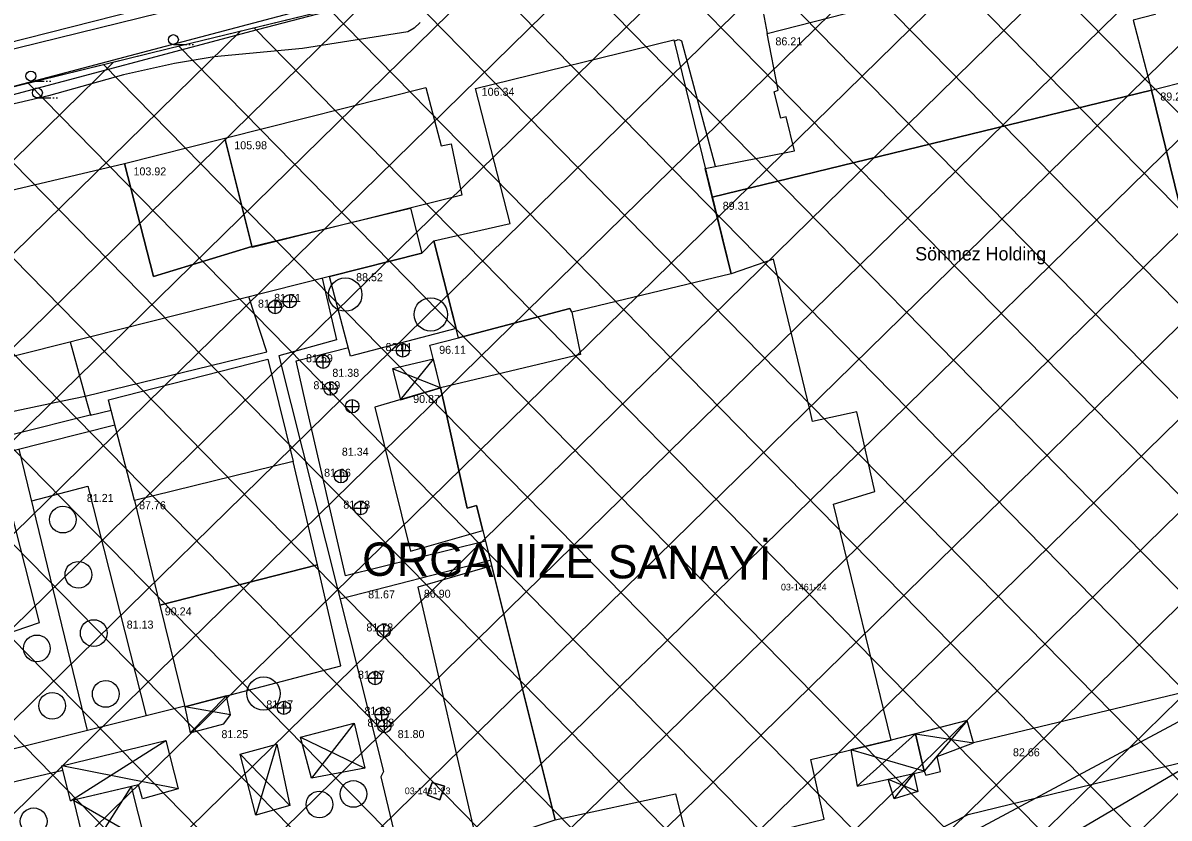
# Model space of a CAD drawing. Extents: x 412225 to 413380, y 4456471 to 4457189.
# Drawn here: x 412361 to 412532.8, y 4456532.7 to 4456651.9 of the extents above; entities that cross this region are included whole.
import ezdxf

# ---------------------------------------------------------------- set-up
doc = ezdxf.new("R2010")
doc.units = 0
for name, color, linetype in [('0_HALİHAZIR', 7, 'Continuous'), ('0_KADASTRO', 7, 'Continuous'), ('ADA_KOCEPHE', 7, 'Continuous'), ('KALDIRIM', 7, 'Continuous'), ('KST_ENERJI_NAKIL_HAT', 7, 'Continuous'), ('Level 35', 7, 'Continuous'), ('YAZI_FONKSIYON', 7, 'Continuous')]:
    doc.layers.add(name, color=color, linetype=linetype)

msp = doc.modelspace()

# ---------------------------------------------------------------- linework, layer by layer
at = {"layer": '0_HALİHAZIR'}
for p, q in [((412383.59, 4456648.67), (412385.59, 4456648.67)), ((412385.89, 4456648.67), (412386.09, 4456648.67)), ((412386.39, 4456648.67), (412386.59, 4456648.67)), ((412362.23, 4456643.21), (412364.23, 4456643.21)), ((412364.53, 4456643.21), (412364.73, 4456643.21)), ((412365.03, 4456643.21), (412365.23, 4456643.21)), ((412363.2, 4456640.68), (412365.2, 4456640.68)), ((412365.5, 4456640.68), (412365.7, 4456640.68)), ((412366, 4456640.68), (412366.2, 4456640.68)), ((412401.04, 4456609.18), (412401.04, 4456611.18)), ((412397.83, 4456609.3), (412399.83, 4456609.3)), ((412398.85, 4456608.31), (412398.85, 4456610.31)), ((412400.02, 4456610.17), (412402.03, 4456610.17)), ((412417.99, 4456601.8), (412417.99, 4456603.8)), ((412406.04, 4456600.13), (412406.04, 4456602.13)), ((412416.97, 4456602.79), (412418.97, 4456602.79)), ((412405.02, 4456601.12), (412407.02, 4456601.12)), ((412417.61, 4456595.42), (412422.56, 4456601.53)), ((412423.63, 4456597.19), (412416.43, 4456600.08)), ((412406.14, 4456597.07), (412408.14, 4456597.07)), ((412407.16, 4456596.08), (412407.16, 4456598.08)), ((412410.42, 4456593.44), (412410.42, 4456595.44)), ((412409.4, 4456594.43), (412411.4, 4456594.43)), ((412408.73, 4456582.96), (412408.73, 4456584.96)), ((412407.71, 4456583.95), (412409.71, 4456583.95)), ((412411.67, 4456578.17), (412411.67, 4456580.17)), ((412410.65, 4456579.16), (412412.65, 4456579.16)), ((412415.13, 4456559.76), (412415.13, 4456561.76)), ((412414.11, 4456560.75), (412416.11, 4456560.75)), ((412413.84, 4456552.67), (412413.84, 4456554.67)), ((412412.82, 4456553.66), (412414.82, 4456553.66)), ((412386.11, 4456545.48), (412391.53, 4456551.01)), ((412392.16, 4456548.19), (412385.31, 4456549.38)), ((412399.14, 4456549.22), (412401.14, 4456549.22)), ((412400.16, 4456548.23), (412400.16, 4456550.23)), ((412414.81, 4456547.26), (412414.81, 4456549.26)), ((412413.79, 4456548.25), (412415.79, 4456548.25)), ((412415.24, 4456545.49), (412415.24, 4456547.49)), ((412502.59, 4456547.31), (412496.13, 4456539.75)), ((412410.7, 4456546.95), (412404.27, 4456538.68)), ((412414.22, 4456546.48), (412416.22, 4456546.48)), ((412368.16, 4456535.26), (412382.47, 4456544.31)), ((412399.09, 4456543.76), (412395.95, 4456533.15)), ((412402.65, 4456544.85), (412412.28, 4456540.19)), ((412486.09, 4456537.5), (412494.82, 4456545.31)), ((412494.82, 4456545.31), (412503.52, 4456543.97)), ((412401.04, 4456534.57), (412393.62, 4456542.26)), ((412496.13, 4456539.75), (412485.11, 4456542.91)), ((412384.29, 4456537.09), (412366.85, 4456540.51)), ((412490.74, 4456538.54), (412495.16, 4456536.69)), ((412491.65, 4456535.58), (412494.57, 4456539.4)), ((412370.66, 4456526.93), (412377.33, 4456537.43)), ((412368.61, 4456535.37), (412379.42, 4456529.15))]:
    msp.add_line(p, q, dxfattribs=at)
for points in [[(412503.46, 4456678.24), (412469.03, 4456669.65), (412438.84, 4456662.52), (412415.68, 4456657.24), (412394.67, 4456651.63), (412365.71, 4456643.97), (412342.49, 4456637.89), (412316.39, 4456631.19), (412296.71, 4456626.06), (412285.88, 4456622.98), (412282.22, 4456621.58), (412278.94, 4456619.91), (412278.4, 4456619.56)], [(412357.12, 4456640.53), (412396.21, 4456650.96), (412438.91, 4456662.09), (412504.33, 4456676.98)], [(412529.7, 4456655.24), (412525.79, 4456669.17), (412525.27, 4456670.1), (412524.21, 4456670.56), (412523.52, 4456670.53), (412491.27, 4456661.69), (412473.27, 4456656.15), (412472.52, 4456655.76), (412472.02, 4456655.25), (412471.86, 4456654.69), (412471.82, 4456654.34), (412472.61, 4456650.34)], [(412278.48, 4456627.16), (412279.26, 4456627.57), (412281.29, 4456628.76), (412283.94, 4456629.85), (412286.89, 4456630.78), (412291.55, 4456632.15), (412297.64, 4456633.61), (412308.19, 4456636.21), (412319.38, 4456638.69), (412351.46, 4456647.07), (412388.33, 4456656.47)], [(412420.6, 4456651.99), (412419.67, 4456651.14), (412418.73, 4456650.58), (412402.95, 4456648.1), (412389.72, 4456646.85), (412383.74, 4456645.86), (412376.09, 4456644.14), (412364.86, 4456640.98), (412346.84, 4456636.79), (412322.19, 4456630.84), (412300.47, 4456625.56), (412292.91, 4456623.54), (412286.97, 4456621.46), (412284.52, 4456620.61), (412283.67, 4456620.07), (412285.65, 4456615.33), (412279.53, 4456612.2), (412278.3, 4456611.35)], [(412464.87, 4456630.42), (412459.81, 4456649.2), (412459.48, 4456649.36), (412459.21, 4456649.37), (412458.66, 4456649.12)], [(412542.12, 4456593.2), (412530.21, 4456641.83), (412545.79, 4456645.85), (412558.92, 4456593)], [(412478.97, 4456593.94), (412473.55, 4456616.5), (412467.17, 4456614.32), (412464.37, 4456625.79), (412530.21, 4456641.83), (412530.21, 4456641.83), (412542.12, 4456593.2)], [(412324.88, 4456595.74), (412318.66, 4456617.26), (412376.28, 4456630.84), (412380.61, 4456613.92), (412395.35, 4456618.38), (412419.14, 4456624.17), (412420.81, 4456617.41), (412334.6, 4456595.63)], [(412478.97, 4456593.94), (412473.55, 4456616.5), (412467.17, 4456614.32), (412443.29, 4456608.57), (412444.61, 4456602.2), (412423.63, 4456597.19), (412424.21, 4456594.58)], [(412405.9, 4456613.64), (412408.02, 4456604.42), (412399.41, 4456601.99), (412401.21, 4456594.85)], [(412366.99, 4456595.25), (412370.37, 4456595.95), (412397.62, 4456602.61), (412394.89, 4456610.86)], [(412368.12, 4456604.1), (412370.58, 4456595.21)], [(412403.46, 4456594.82), (412401.98, 4456601.28), (412409.82, 4456603.28)], [(412373.92, 4456595.17), (412373.87, 4456595.39), (412397.74, 4456601.51), (412399.38, 4456594.87)], [(412424.21, 4456594.58), (412423.63, 4456597.19), (412415.11, 4456594.69)], [(412359.23, 4456590.13), (412357.98, 4456593.38), (412366.99, 4456595.25)], [(412370.58, 4456595.21), (412371.16, 4456593.12), (412374.25, 4456593.88)], [(412399.38, 4456594.87), (412401.53, 4456586.16), (412377.74, 4456580.31), (412373.92, 4456595.17)], [(412401.21, 4456594.85), (412415.06, 4456539.7), (412414.66, 4456538.87), (412422.31, 4456506.91), (412435.88, 4456510.46)], [(412430.38, 4456574.21), (412409.37, 4456569.03), (412403.46, 4456594.82)], [(412415.11, 4456594.69), (412413.79, 4456594.3), (412419.15, 4456572.7), (412429.98, 4456575.8), (412429.04, 4456579.59), (412427.64, 4456579.17), (412424.21, 4456594.58)], [(412424.21, 4456594.58), (412427.64, 4456579.17), (412429.04, 4456579.59), (412440.8, 4456532.45), (412458.84, 4456536.33), (412461.04, 4456527.62), (412481.15, 4456532.54), (412479.12, 4456541.46), (412491.17, 4456544.37), (412482.53, 4456579.78), (412488.75, 4456581.68), (412486.01, 4456593.59), (412479.39, 4456592.17), (412478.97, 4456593.94)], [(412542.12, 4456593.2), (412551.37, 4456555.47), (412503.52, 4456543.97), (412502.59, 4456547.31), (412491.17, 4456544.37), (412482.53, 4456579.78), (412488.75, 4456581.68), (412486.01, 4456593.59), (412479.39, 4456592.17), (412478.97, 4456593.94)], [(412371.3, 4456593.16), (412347.41, 4456587.17), (412327.9, 4456582.59), (412325.92, 4456589.78)], [(412456.28, 4456505.44), (412618.62, 4456592.3)], [(412327.62, 4456575.47), (412329.07, 4456580.11), (412374.83, 4456591.65)], [(412353.88, 4456541.63), (412349.32, 4456557.19), (412363.52, 4456562.02), (412357.07, 4456587.17)], [(412370.74, 4456545.84), (412360.47, 4456588.03)], [(412362.36, 4456580.26), (412370.79, 4456582.44), (412379.52, 4456548.03)], [(412408.56, 4456565.59), (412431.08, 4456571.38)], [(412385.29, 4456549.47), (412342.5, 4456538.8)], [(412371.14, 4456546.26), (412371.14, 4456546.26)], [(412370.58, 4456527.26), (412358.28, 4456523.98), (412354.88, 4456537.05), (412367.01, 4456539.87)]]:
    msp.add_lwpolyline(points, dxfattribs=at)
for points in [[(412464.37, 4456625.79), (412463.31, 4456630.11), (412476.68, 4456632.74), (412475.42, 4456637.82), (412474.64, 4456637.64), (412473.64, 4456641.59), (412474.26, 4456641.83), (412472.61, 4456650.34), (412495.86, 4456656.35), (412494.93, 4456659.32), (412513.06, 4456663.86), (412514.11, 4456660.71), (412526.01, 4456664.05), (412528.31, 4456654.98), (412530.33, 4456655.36), (412530.77, 4456653.21), (412527.45, 4456652.36), (412530.21, 4456641.83)], [(412458.6, 4456649.38), (412467.17, 4456614.32), (412443.29, 4456608.57), (412443.03, 4456609.08), (412426.35, 4456604.69), (412422.62, 4456619.23), (412434.07, 4456621.87), (412428.86, 4456642.07)], [(412391.28, 4456634.64), (412421.41, 4456642.26), (412423.73, 4456633.48), (412425.23, 4456633.79), (412426.81, 4456626.08), (412395.38, 4456618.26)], [(412395.35, 4456618.38), (412380.61, 4456613.92), (412376.28, 4456630.84), (412391.28, 4456634.64)], [(412410.16, 4456601.96), (412407, 4456613.92), (412420.81, 4456617.41), (412422.62, 4456619.23), (412422.62, 4456619.23), (412425.99, 4456606.11)], [(412443.03, 4456609.08), (412443.29, 4456608.57), (412444.61, 4456602.2), (412423.63, 4456597.19), (412422.04, 4456603.61), (412426.35, 4456604.69)], [(412416.43, 4456600.08), (412417.61, 4456595.42), (412423.63, 4456597.19), (412423.63, 4456597.19), (412422.56, 4456601.53)], [(412377.74, 4456580.31), (412381.54, 4456564.64), (412405.21, 4456570.65), (412401.53, 4456586.16)], [(412381.54, 4456564.64), (412385.31, 4456549.38), (412408.68, 4456555.52), (412405.21, 4456570.65)], [(412429.15, 4456528.55), (412440.8, 4456532.45), (412431.3, 4456570.53), (412420.25, 4456567.34)], [(412386.11, 4456545.48), (412391.16, 4456546.85), (412392.16, 4456548.19), (412391.53, 4456551.01), (412385.31, 4456549.38)], [(412496.37, 4456539.11), (412498.59, 4456539.67), (412498.05, 4456541.95), (412503.52, 4456543.97), (412502.59, 4456547.31), (412494.82, 4456545.31), (412496.13, 4456539.75)], [(412402.65, 4456544.85), (412410.7, 4456546.95), (412412.28, 4456540.19), (412404.27, 4456538.68)], [(412382.47, 4456544.31), (412384.29, 4456537.09), (412378.94, 4456535.6), (412378.34, 4456537.66), (412368.16, 4456535.26), (412366.85, 4456540.51)], [(412393.62, 4456542.26), (412399.09, 4456543.76), (412401.04, 4456534.57), (412395.95, 4456533.15)], [(412486.09, 4456537.5), (412496.13, 4456539.75), (412494.82, 4456545.31), (412491.17, 4456544.37), (412485.11, 4456542.91)], [(412472.63, 4456513.97), (412471.89, 4456517.48), (412502.72, 4456533.23), (412536.11, 4456541.4), (412544.04, 4456539.97), (412539.34, 4456529.12), (412503.11, 4456520.4)], [(412491.65, 4456535.58), (412490.74, 4456538.54), (412494.57, 4456539.4), (412495.16, 4456536.69)], [(412368.61, 4456535.37), (412370.66, 4456526.93), (412379.42, 4456529.15), (412377.33, 4456537.43)]]:
    msp.add_lwpolyline(points, close=True, dxfattribs=at)
for centre, radius in [((412383.59, 4456649.42), 0.75), ((412362.23, 4456643.96), 0.75), ((412363.2, 4456641.43), 0.75), ((412409.36, 4456611.18), 2.5), ((412401.03, 4456610.19), 1), ((412422.16, 4456608.22), 2.5), ((412398.84, 4456609.32), 1), ((412417.98, 4456602.81), 1), ((412406.03, 4456601.13), 1), ((412407.15, 4456597.09), 1), ((412410.4, 4456594.45), 1), ((412408.71, 4456583.96), 1), ((412411.66, 4456579.18), 1), ((412367.03, 4456577.45), 2), ((412369.35, 4456569.18), 2), ((412371.65, 4456560.44), 2), ((412415.11, 4456560.77), 1), ((412363.13, 4456558.14), 2), ((412413.83, 4456553.68), 1), ((412373.45, 4456551.31), 2), ((412397.1, 4456551.36), 2.5), ((412365.43, 4456549.54), 2), ((412400.15, 4456549.23), 1), ((412414.8, 4456548.27), 1), ((412415.23, 4456546.49), 1), ((412410.58, 4456536.31), 2), ((412405.48, 4456534.74), 2), ((412362.65, 4456532.21), 2)]:
    msp.add_circle(centre, radius, dxfattribs=at)
at = {"layer": '0_KADASTRO'}
msp.add_lwpolyline([(412239.08, 4456522.92), (412241.81, 4456532.11), (412244.3, 4456540.07), (412253.47, 4456569.46), (412258.13, 4456584.22), (412263.51, 4456600.42), (412265.57, 4456606.92), (412266.96, 4456610.88), (412276.22, 4456617.55), (412284.56, 4456623.15), (412289.25, 4456625.07), (412382.85, 4456648.08), (412458, 4456666.39), (412467.04, 4456668.7), (412522.03, 4456682.07), (412533.88, 4456684.99)], dxfattribs=at)
for points in [[(412421.66, 4456536.14), (412422.38, 4456538.01), (412424.24, 4456537.49), (412423.52, 4456535.42)], [(412421.66, 4456536.14), (412423.52, 4456535.42), (412424.24, 4456537.49), (412422.38, 4456538.01)]]:
    msp.add_lwpolyline(points, close=True, dxfattribs=at)
at = {"layer": 'ADA_KOCEPHE'}
for p, q in [((412382.85, 4456648.08), (412458, 4456666.39)), ((412382.85, 4456648.08), (412458, 4456666.39)), ((412289.25, 4456625.07), (412382.85, 4456648.08)), ((412289.25, 4456625.07), (412382.85, 4456648.08))]:
    msp.add_line(p, q, dxfattribs=at)
at = {"layer": 'KALDIRIM'}
msp.add_lwpolyline([(412281.12, 4456628.74), (412381.54, 4456653.42), (412456.67, 4456671.73), (412465.71, 4456674.04), (412520.72, 4456687.41), (412532.49, 4456690.31), (412561.23, 4456698.22)], dxfattribs=at)
at = {"layer": 'KST_ENERJI_NAKIL_HAT'}
msp.add_line((412440.9, 4456484.9), (412669.03, 4456618.99), dxfattribs=at)
at = {"layer": 'Level 35'}
for p, q in [((412355.84, 4456487.65), (412566.39, 4456693.93)), ((412368.18, 4456485.74), (412576.92, 4456690.25)), ((412351.91, 4456497.8), (412546.52, 4456688.47)), ((412340.38, 4456500.51), (412526.94, 4456683.28)), ((412382.31, 4456485.58), (412583.91, 4456683.1)), ((412328.53, 4456502.89), (412507.91, 4456678.64)), ((412396.43, 4456485.42), (412590.9, 4456675.95)), ((412616.01, 4456554.95), (412497.34, 4456676.07)), ((412316.68, 4456505.28), (412488.9, 4456674.02)), ((412611.72, 4456545.03), (412486.03, 4456673.32)), ((412304.82, 4456507.67), (412469.9, 4456669.39)), ((412607.44, 4456535.11), (412474.73, 4456670.57)), ((412410.55, 4456485.25), (412597.88, 4456668.79)), ((412603.16, 4456525.19), (412463.45, 4456667.78)), ((412292.97, 4456510.05), (412450.73, 4456664.62)), ((412598.88, 4456515.27), (412452.2, 4456664.98)), ((412594.6, 4456505.35), (412440.9, 4456662.22)), ((412424.67, 4456485.09), (412604.86, 4456661.62)), ((412281.11, 4456512.44), (412431.71, 4456659.99)), ((412589.81, 4456495.94), (412429.6, 4456659.47)), ((412269.26, 4456514.82), (412412.7, 4456655.35)), ((412550, 4456522.29), (412418.3, 4456656.72)), ((412531.23, 4456527.16), (412407, 4456653.96)), ((412438.8, 4456484.93), (412612.59, 4456655.2)), ((412257.41, 4456517.21), (412393.68, 4456650.72)), ((412519.99, 4456524.35), (412395.7, 4456651.21)), ((412508.74, 4456521.54), (412384.39, 4456648.46)), ((412452.92, 4456484.76), (412620.47, 4456648.92)), ((412245.55, 4456519.59), (412374.63, 4456646.06)), ((412505.37, 4456510.69), (412373.11, 4456645.69)), ((412509.02, 4456492.67), (412361.83, 4456642.91)), ((412467.04, 4456484.6), (412628.34, 4456642.63)), ((412503.34, 4456484.18), (412350.54, 4456640.14)), ((412489.18, 4456484.35), (412339.26, 4456637.36)), ((412522.55, 4456524.99), (412636.22, 4456636.35)), ((412475.02, 4456484.51), (412327.98, 4456634.59)), ((412460.86, 4456484.67), (412316.7, 4456631.82)), ((412446.7, 4456484.84), (412305.41, 4456629.04)), ((412432.54, 4456485), (412294.13, 4456626.27)), ((412418.38, 4456485.16), (412283.73, 4456622.6))]:
    msp.add_line(p, q, dxfattribs=at)

# ---------------------------------------------------------------- texts
at = {"layer": '0_HALİHAZIR'}
for s, height, p in [('86.21', 1.2, (412473.83, 4456648.56)), ('106.34', 1.2, (412429.8, 4456641)), ('89.28', 1.2, (412531.52, 4456640.29)), ('105.98', 1.2, (412392.72, 4456632.98)), ('103.92', 1.2, (412377.61, 4456629.06)), ('89.31', 1.2, (412465.93, 4456623.9)), ('Sönmez Holding', 2, (412494.78, 4456616.31)), ('88.52', 1.2, (412410.98, 4456613.2)), ('81.71', 1.2, (412398.69, 4456610.1)), ('81.76', 1.2, (412396.27, 4456609.23)), ('82.01', 1.2, (412415.39, 4456602.72)), ('81.59', 1.2, (412403.47, 4456601.05)), ('96.11', 1.2, (412423.43, 4456602.31)), ('81.38', 1.2, (412407.42, 4456598.86)), ('81.59', 1.2, (412404.58, 4456597)), ('90.87', 1.2, (412419.53, 4456594.94)), ('81.34', 1.2, (412408.84, 4456587.03)), ('81.66', 1.2, (412406.18, 4456583.88)), ('81.21', 1.2, (412370.62, 4456580.1)), ('87.76', 1.2, (412378.45, 4456579)), ('81.78', 1.2, (412409.06, 4456579.09)), ('03-1461-24', 1, (412474.66, 4456566.83)), ('81.67', 1.2, (412412.78, 4456565.64)), ('86.90', 1.2, (412421.13, 4456565.74)), ('90.24', 1.2, (412382.3, 4456563.09)), ('81.13', 1.2, (412376.59, 4456561.11)), ('81.78', 1.2, (412412.52, 4456560.68)), ('81.97', 1.2, (412411.26, 4456553.59)), ('81.47', 1.2, (412397.52, 4456549.15)), ('81.89', 1.2, (412412.23, 4456548.18)), ('81.93', 1.2, (412412.67, 4456546.41)), ('81.25', 1.2, (412390.79, 4456544.68)), ('81.80', 1.2, (412417.21, 4456544.69)), ('82.66', 1.2, (412509.43, 4456541.96)), ('03-1461-23', 1, (412418.28, 4456536.28))]:
    msp.add_text(s, height=height, dxfattribs=at).set_placement(p)
at = {"layer": '0_KADASTRO'}
for s, p in [('03-1461-24', (412474.66, 4456566.83)), ('03-1461-23', (412418.28, 4456536.28))]:
    msp.add_text(s, height=1, dxfattribs=at).set_placement(p)
at = {"layer": 'YAZI_FONKSIYON'}
msp.add_text('ORGANİZE SANAYİ', height=5, rotation=359.4136, dxfattribs=at).set_placement((412411.88, 4456569.04))
msp.add_text('ORGANİZE SANAYİ', height=5, rotation=359.4136, dxfattribs=at).set_placement((412411.88, 4456569.04))

doc.saveas('drawing.dxf')
